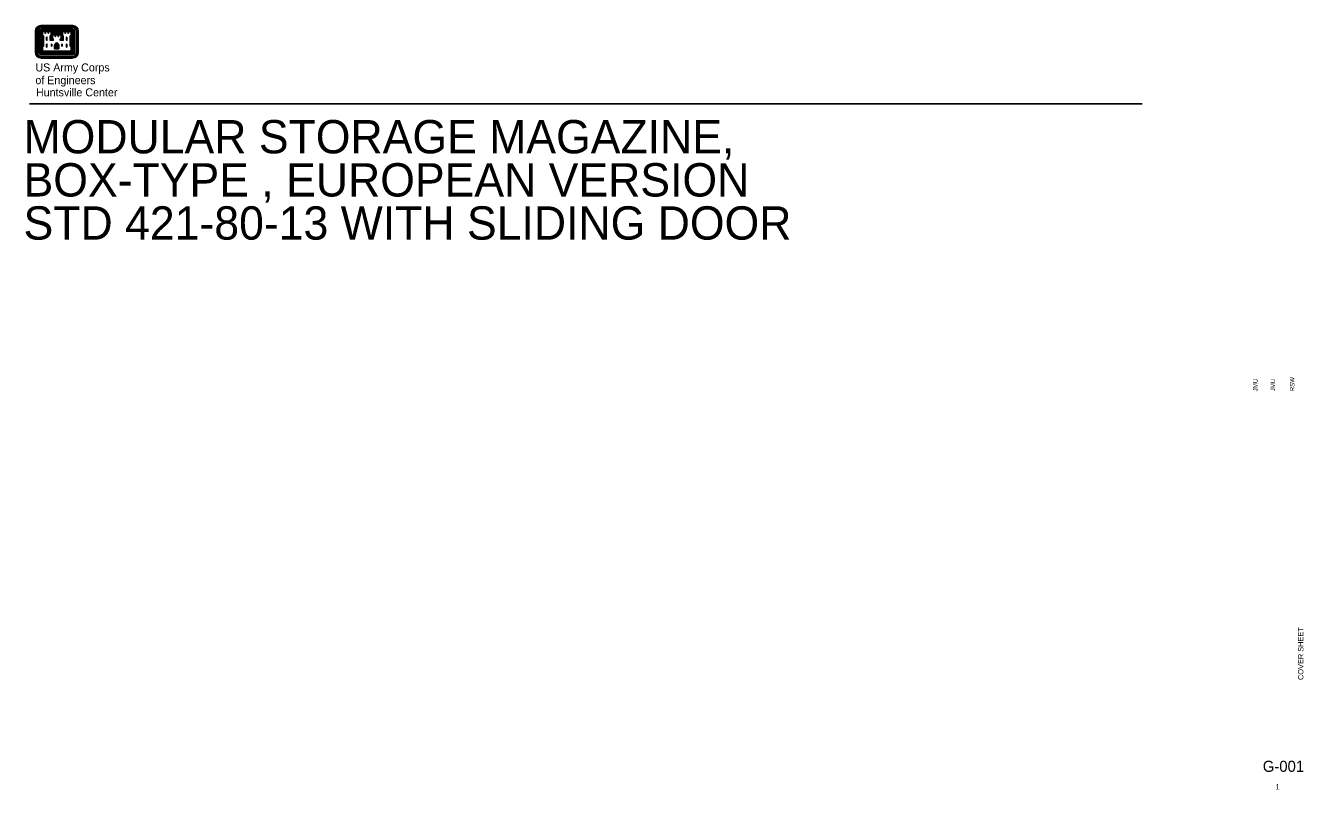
# Model space of a CAD drawing. Extents: x 0.29 to 2.69, y 0.14 to 1.57.
import ezdxf

# ---------------------------------------------------------------- set-up
doc = ezdxf.new("R2010")
doc.units = 0
doc.layers.add('G-ANNO-TEXT', color=7, linetype='Continuous')
doc.layers.add('G-ANNO-TTLB', color=7, linetype='Continuous')

msp = doc.modelspace()

# ---------------------------------------------------------------- linework, layer by layer
at = {"layer": 'G-ANNO-TEXT'}
msp.add_line((0.3008, 1.4245), (2.3865, 1.4245), dxfattribs=at)
at = {"layer": 'G-ANNO-TTLB'}
for p, q in [((0.3116, 1.5605), (0.3116, 1.5206)), ((0.3123, 1.5605), (0.3123, 1.5206)), ((0.3132, 1.5605), (0.3132, 1.5206)), ((0.314, 1.5605), (0.314, 1.5206)), ((0.3148, 1.5605), (0.3148, 1.5206)), ((0.3182, 1.5605), (0.3182, 1.5206)), ((0.3191, 1.5605), (0.3191, 1.5206)), ((0.3199, 1.5605), (0.3199, 1.5206)), ((0.3208, 1.5605), (0.3208, 1.5206)), ((0.3216, 1.5605), (0.3216, 1.5206)), ((0.3813, 1.5711), (0.3222, 1.5711)), ((0.3813, 1.5704), (0.3222, 1.5704)), ((0.3813, 1.5696), (0.3222, 1.5696)), ((0.3813, 1.5688), (0.3222, 1.5688)), ((0.3813, 1.5679), (0.3222, 1.5679)), ((0.3813, 1.5646), (0.3222, 1.5646)), ((0.3813, 1.5637), (0.3222, 1.5637)), ((0.3813, 1.5628), (0.3222, 1.5628)), ((0.3813, 1.562), (0.3222, 1.562)), ((0.3813, 1.5612), (0.3222, 1.5612)), ((0.3224, 1.5605), (0.3224, 1.5209)), ((0.3233, 1.5605), (0.3233, 1.5218)), ((0.3425, 1.5603), (0.3608, 1.5603)), ((0.3425, 1.5595), (0.3608, 1.5595)), ((0.3425, 1.5588), (0.3608, 1.5588)), ((0.3425, 1.5578), (0.3608, 1.5578)), ((0.3802, 1.5605), (0.3802, 1.5218)), ((0.381, 1.5605), (0.381, 1.5209)), ((0.3818, 1.5605), (0.3818, 1.5206)), ((0.3827, 1.5605), (0.3827, 1.5206)), ((0.3836, 1.5605), (0.3836, 1.5206)), ((0.3844, 1.5605), (0.3844, 1.5206)), ((0.3852, 1.5605), (0.3852, 1.5206)), ((0.3886, 1.5605), (0.3886, 1.5206)), ((0.3895, 1.5605), (0.3895, 1.5206)), ((0.3903, 1.5605), (0.3903, 1.5206)), ((0.3911, 1.5605), (0.3911, 1.5206)), ((0.3917, 1.5605), (0.3917, 1.5206)), ((0.324, 1.5521), (0.324, 1.5316)), ((0.3248, 1.5512), (0.3248, 1.5326)), ((0.3425, 1.557), (0.3608, 1.557)), ((0.3425, 1.5562), (0.3608, 1.5562)), ((0.3425, 1.5553), (0.3608, 1.5553)), ((0.3477, 1.5275), (0.3477, 1.534)), ((0.3486, 1.5275), (0.3486, 1.534)), ((0.3494, 1.5275), (0.3494, 1.534)), ((0.3503, 1.5275), (0.3503, 1.534)), ((0.3512, 1.5275), (0.3512, 1.534)), ((0.3523, 1.5275), (0.3523, 1.534)), ((0.3531, 1.5275), (0.3531, 1.534)), ((0.354, 1.5275), (0.354, 1.534)), ((0.3548, 1.5275), (0.3548, 1.534)), ((0.3557, 1.5275), (0.3557, 1.534)), ((0.3787, 1.5512), (0.3787, 1.5326)), ((0.3794, 1.552), (0.3794, 1.5318)), ((0.3813, 1.52), (0.3222, 1.52)), ((0.3813, 1.5192), (0.3222, 1.5192)), ((0.3813, 1.5183), (0.3222, 1.5183)), ((0.3813, 1.5175), (0.3222, 1.5175)), ((0.3813, 1.5167), (0.3222, 1.5167)), ((0.3813, 1.5132), (0.3222, 1.5132)), ((0.3813, 1.5124), (0.3222, 1.5124)), ((0.3813, 1.5116), (0.3222, 1.5116)), ((0.3813, 1.5108), (0.3222, 1.5108)), ((0.3813, 1.5101), (0.3222, 1.5101)), ((0.381, 1.5209), (0.3224, 1.5209)), ((0.3802, 1.5218), (0.3233, 1.5218)), ((0.3477, 1.5275), (0.3557, 1.5275))]:
    msp.add_line(p, q, dxfattribs=at)
for points in [[(0.324, 1.5605), (0.324, 1.5529), (0.3257, 1.5512), (0.3257, 1.5326), (0.324, 1.5308), (0.324, 1.5223), (0.3795, 1.5223), (0.3795, 1.5308), (0.3777, 1.5326), (0.3777, 1.5512), (0.3795, 1.5529), (0.3795, 1.5605), (0.3722, 1.5605), (0.3665, 1.5605), (0.3613, 1.5605), (0.3613, 1.5529), (0.3631, 1.5512), (0.3631, 1.5445), (0.3591, 1.5445), (0.3591, 1.5451), (0.3608, 1.5468), (0.3608, 1.5544), (0.3534, 1.5544), (0.3478, 1.5544), (0.3425, 1.5544), (0.3425, 1.5468), (0.3443, 1.5451), (0.3443, 1.5445), (0.3403, 1.5445), (0.3403, 1.5512), (0.3421, 1.5529), (0.3421, 1.5605), (0.3346, 1.5605), (0.329, 1.5605), (0.324, 1.5605)], [(0.3248, 1.5597), (0.3248, 1.5533), (0.3265, 1.5515), (0.3265, 1.5322), (0.3248, 1.5305), (0.3248, 1.5233), (0.3787, 1.5233), (0.3787, 1.5305), (0.377, 1.5322), (0.377, 1.5515), (0.3787, 1.5533), (0.3787, 1.5597), (0.3735, 1.5597), (0.3735, 1.5567), (0.373, 1.5567), (0.373, 1.5597), (0.3679, 1.5597), (0.3679, 1.5567), (0.3674, 1.5567), (0.3674, 1.5597), (0.3622, 1.5597), (0.3622, 1.5533), (0.3639, 1.5515), (0.3639, 1.5436), (0.3583, 1.5436), (0.3583, 1.5455), (0.36, 1.5471), (0.36, 1.5537), (0.3548, 1.5537), (0.3548, 1.5506), (0.3543, 1.5506), (0.3543, 1.5537), (0.3491, 1.5537), (0.3491, 1.5506), (0.3486, 1.5506), (0.3486, 1.5537), (0.3435, 1.5537), (0.3435, 1.5471), (0.3452, 1.5455), (0.3452, 1.5436), (0.3394, 1.5436), (0.3394, 1.5515), (0.3412, 1.5533), (0.3412, 1.5597), (0.3361, 1.5597), (0.3361, 1.5567), (0.3356, 1.5567), (0.3356, 1.5597), (0.3303, 1.5597), (0.3303, 1.5567), (0.3299, 1.5567), (0.3299, 1.5597), (0.3248, 1.5597)], [(0.3327, 1.5493), (0.3327, 1.5436), (0.3332, 1.5436), (0.3332, 1.5493), (0.3327, 1.5493)], [(0.3327, 1.5362), (0.3327, 1.5306), (0.3332, 1.5306), (0.3332, 1.5362), (0.3327, 1.5362)], [(0.3417, 1.5513), (0.3411, 1.5508), (0.3411, 1.5452), (0.343, 1.5452), (0.3417, 1.5465), (0.3417, 1.5514)], [(0.3416, 1.5362), (0.3416, 1.5324), (0.3422, 1.5324), (0.3422, 1.5362), (0.3416, 1.5362)], [(0.3617, 1.5513), (0.3622, 1.5508), (0.3622, 1.5452), (0.3605, 1.5452), (0.3617, 1.5465), (0.3617, 1.5514)], [(0.3617, 1.5362), (0.3617, 1.5324), (0.3612, 1.5324), (0.3612, 1.5362), (0.3617, 1.5362)], [(0.3707, 1.5493), (0.3707, 1.5436), (0.3701, 1.5436), (0.3701, 1.5493), (0.3707, 1.5493)], [(0.3707, 1.5362), (0.3707, 1.5306), (0.3701, 1.5306), (0.3701, 1.5362), (0.3707, 1.5362)]]:
    msp.add_lwpolyline(points, dxfattribs=at)
for centre, major_axis, start_param, end_param in [((0.3221, 1.5606), (-0.0104, 0), 4.712389, 6.283185), ((0.3221, 1.5606), (-0.00984, 0), 4.712389, 6.283185), ((0.3221, 1.5606), (-0.00899, 0), 4.712389, 6.283185), ((0.3221, 1.5606), (-0.00815, 0), 4.712389, 6.283185), ((0.3221, 1.5606), (-0.0073, 0), 4.712389, 6.283185), ((0.3221, 1.5606), (-0.00392, 0), 4.712389, 6.283185), ((0.3221, 1.5606), (-0.00307, 0), 4.712389, 6.283185), ((0.3221, 1.5606), (-0.00222, 0), 4.712389, 6.283185), ((0.3221, 1.5606), (0.00138, 0), 1.570796, 3.141593), ((0.3221, 1.5606), (-0.000532, 0), 4.712389, 6.283185), ((0.3813, 1.5606), (-0.0104, 0), 3.141593, 4.712389), ((0.3813, 1.5606), (0.00984, 0), 0, 1.570796), ((0.3813, 1.5606), (0.00899, 0), 0, 1.570796), ((0.3813, 1.5606), (0.00815, 0), 0, 1.570796), ((0.3813, 1.5606), (0.0073, 0), 0, 1.570796), ((0.3813, 1.5606), (-0.00392, 0), 3.141593, 4.712389), ((0.3813, 1.5606), (-0.00307, 0), 3.141593, 4.712389), ((0.3813, 1.5606), (-0.00222, 0), 3.141593, 4.712389), ((0.3813, 1.5606), (-0.00138, 0), 3.141593, 4.712389), ((0.3813, 1.5606), (-0.000532, 0), 3.141593, 4.712389), ((0.3532, 1.5336), (0.00541, 0), 1.844255, 3.072783), ((0.3532, 1.5336), (-0.00457, 0), 4.947481, 6.214375), ((0.3532, 1.5336), (-0.00372, 0), 4.947481, 6.214375), ((0.3532, 1.5336), (-0.00288, 0), 4.947481, 6.214375), ((0.3502, 1.5336), (0.00203, 0), 0.06881, 1.335704), ((0.3502, 1.5336), (0.00288, 0), 0.06881, 1.335704), ((0.3502, 1.5336), (-0.00372, 0), 3.210403, 4.477297), ((0.3532, 1.5336), (-0.00203, 0), 4.947481, 6.214375), ((0.3502, 1.5336), (0.00457, 0), 0.06881, 1.335704), ((0.3502, 1.5336), (0.00541, 0), 0.06881, 1.298435), ((0.3221, 1.5206), (0.0104, 0), 3.141593, 4.712389), ((0.3221, 1.5206), (0.00984, 0), 3.141593, 4.712389), ((0.3221, 1.5206), (-0.00899, 0), 0, 1.570796), ((0.3221, 1.5206), (0.00815, 0), 3.141593, 4.712389), ((0.3221, 1.5206), (0.0073, 0), 3.141593, 4.712389), ((0.3221, 1.5206), (0.00392, 0), 3.141593, 4.712389), ((0.3221, 1.5206), (0.00307, 0), 3.141593, 4.712389), ((0.3221, 1.5206), (0.00222, 0), 3.141593, 4.712389), ((0.3221, 1.5206), (0.00138, 0), 3.141593, 4.712389), ((0.3221, 1.5206), (0.000532, 0), 3.141593, 4.712389), ((0.3813, 1.5206), (0.0104, 0), 4.712389, 6.283185), ((0.3813, 1.5206), (0.00392, 0), 4.712389, 6.283185), ((0.3813, 1.5206), (0.00307, 0), 4.712389, 6.283185), ((0.3813, 1.5206), (0.00222, 0), 4.712389, 6.283185), ((0.3813, 1.5206), (0.00138, 0), 4.712389, 6.283185), ((0.3813, 1.5206), (0.000532, 0), 4.712389, 6.283185), ((0.3813, 1.5206), (0.0073, 0), 4.712389, 6.283185), ((0.3813, 1.5206), (0.00815, 0), 4.712389, 6.283185), ((0.3813, 1.5206), (0.00899, 0), 4.712389, 6.283185), ((0.3813, 1.5206), (0.00984, 0), 4.712389, 6.283185)]:
    msp.add_ellipse(centre, major_axis=major_axis, ratio=0.999936, start_param=start_param, end_param=end_param, dxfattribs=at)

# ---------------------------------------------------------------- texts
for s, height, p in [('US Army Corps', 0.015, (0.3116, 1.485)), ('of Engineers', 0.015, (0.3116, 1.4611)), ('Huntsville Center', 0.015, (0.3127, 1.4383)), ('MODULAR STORAGE MAGAZINE, ', 0.0625, (0.2894, 1.3313)), ('BOX-TYPE , EUROPEAN VERSION ', 0.0625, (0.2894, 1.2504)), ('STD 421-80-13 WITH SLIDING DOOR', 0.0625, (0.2894, 1.1695)), ('G-001', 0.02083, (2.6129, 0.1712)), ('1', 0.01, (2.6369, 0.1382))]:
    msp.add_text(s, height=height, dxfattribs=at).set_placement(p)
for s, height, p in [('RSW', 0.00833, (2.6722, 0.885)), ('JMU', 0.00833, (2.603, 0.885)), ('JMU', 0.00833, (2.6359, 0.885)), ('COVER SHEET', 0.01, (2.689, 0.3435))]:
    msp.add_text(s, height=height, rotation=90, dxfattribs=at).set_placement(p)

doc.saveas('drawing.dxf')
